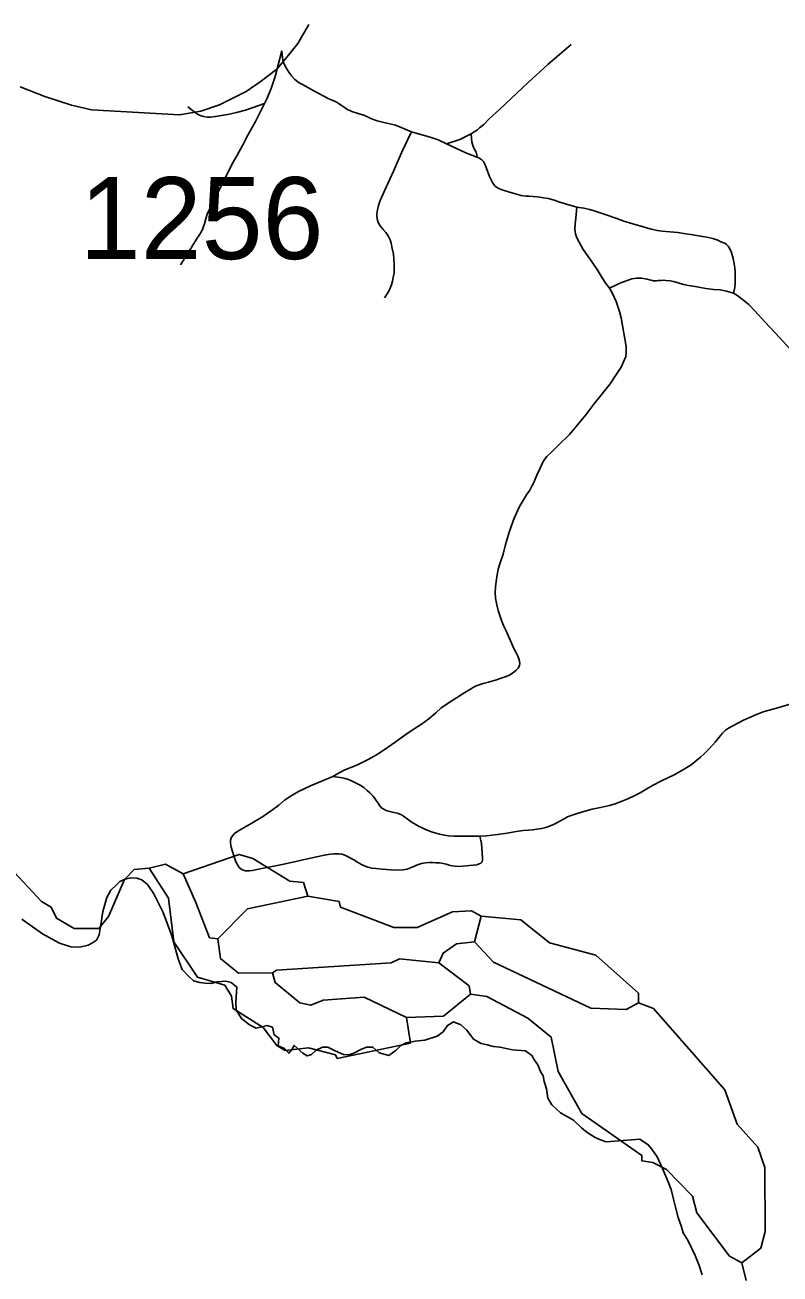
# Model space of a CAD drawing. Extents: x 2093524 to 2270757, y 289120 to 570408.
# Drawn here: x 2117615 to 2122223, y 436115 to 443738 of the extents above; entities that cross this region are included whole.
import ezdxf

# ---------------------------------------------------------------- set-up
doc = ezdxf.new("R2010")
doc.units = 0
for name, color, linetype in [('Exist Boundary Political CountyLine', 7, 'Continuous'), ('Exist Hydrographic Misc Water Feature', 7, 'Continuous'), ('Exist Road Non-System Type 51', 7, 'Continuous'), ('Exist Road Secondary Type 51 Attributed', 7, 'Continuous'), ('Exist Road Secondary Type 51 Number Label', 7, 'Continuous')]:
    doc.layers.add(name, color=color, linetype=linetype)

msp = doc.modelspace()

# ---------------------------------------------------------------- linework, layer by layer
at = {"layer": 'Exist Boundary Political CountyLine'}
for points in [[(2119135.5, 437574), (2119125.8, 437622.2), (2119093.8, 437631.8), (2119026.5, 437615.8), (2118984.8, 437635), (2118936.5, 437673.5), (2118904.5, 437728.1), (2118901.2, 437773), (2118907.8, 437866.1), (2118874, 437893.4), (2118840.2, 437901.4), (2118789, 437898.2), (2118748.8, 437888.6), (2118715.2, 437890.2), (2118683, 437893.4), (2118644.5, 437904.6), (2118614, 437933.5), (2118574, 437973.6), (2118550, 438039.4), (2118511.5, 438179), (2118458.5, 438321.8), (2118402.2, 438434.2), (2118363.8, 438491.9), (2118328.5, 438520.8), (2118298, 438530.5), (2118261, 438532.1), (2118227.5, 438525.6), (2118195.2, 438511.2), (2118171.2, 438488.7), (2118139.2, 438456.6), (2118115, 438413.3), (2118089.5, 438326.7), (2118076.5, 438233.6), (2118068.5, 438185.4), (2118052.5, 438153.3), (2118027, 438135.7), (2118001.2, 438122.8), (2117949.8, 438110), (2117895.2, 438111.6), (2117826.2, 438134.1), (2117722, 438190.2), (2117595.2, 438280.1)], [(2121747.5, 436110.5), (2121729.8, 436166.7), (2121705.8, 436227.7), (2121662.2, 436317.5), (2121632.8, 436365.3), (2121618.8, 436409.2), (2121601.5, 436459.6), (2121586.2, 436523.1), (2121574, 436570.9), (2121557.8, 436630.8), (2121539.5, 436676.8), (2121517.2, 436730.6), (2121495, 436780.5), (2121472.8, 436830.3), (2121440.8, 436876.1), (2121418.5, 436904.2), (2121368.2, 436937.8), (2121265.5, 436929.4), (2121162.8, 436920.9), (2121126.5, 436932.8), (2121094.5, 436948.6), (2121046.2, 436978.4), (2121012.2, 437006.1), (2120962, 437053.9), (2120882.8, 437099), (2120829.8, 437147.2), (2120805.5, 437188.9), (2120797.5, 437245.1), (2120783, 437289), (2120776.8, 437323.7), (2120760.8, 437351), (2120744.8, 437391.1), (2120723.8, 437420), (2120707.8, 437448.9), (2120669.2, 437477.8), (2120590.8, 437482.6), (2120514.2, 437499.5), (2120474.2, 437503.3), (2120436.2, 437513.1), (2120400, 437521), (2120352, 437548.8), (2120335.8, 437570.7), (2120309.5, 437605.8), (2120275.5, 437636.3), (2120229.5, 437654.2), (2120193.8, 437631.9), (2120168, 437593.8), (2120130.2, 437565.8), (2120056.5, 437541.9), (2119995.5, 437535.5), (2119940.8, 437525.9), (2119908.8, 437509.8), (2119880, 437481), (2119835, 437448.9), (2119777.2, 437464.9), (2119738.8, 437500.2), (2119700.2, 437500.2), (2119665, 437484.2), (2119623.2, 437461.7), (2119591, 437452.1), (2119559, 437455.3), (2119507.8, 437477.8), (2119462.8, 437500.2), (2119430.8, 437500.2), (2119392.2, 437481), (2119363.2, 437455.3), (2119337.8, 437445.7), (2119312, 437461.7), (2119257.5, 437509.8), (2119244.5, 437484.2), (2119225.2, 437461.7), (2119199.8, 437490.6), (2119161.2, 437506.7), (2119164.2, 437554.8), (2119135.5, 437574)]]:
    msp.add_lwpolyline(points, dxfattribs=at)
at = {"layer": 'Exist Hydrographic Misc Water Feature'}
for p, q in [((2120357.7, 438141.5), (2120398.7, 438298.1)), ((2119968.7, 437522.7), (2119943.7, 437680.7)), ((2119519.6, 437430), (2119968.7, 437522.7)), ((2122016.8, 436074.4), (2121990.7, 436183.3))]:
    msp.add_line(p, q, dxfattribs=at)
for points in [[(2119340.6, 438421), (2119314.6, 438503.5), (2119231.5, 438511.7), (2119005.6, 438650.7), (2118922.5, 438675.4), (2118581.5, 438557.5)], [(2117774.6, 438353.8), (2117715.6, 438387.8), (2117523.7, 438595)], [(2117774.6, 438353.8), (2117807.6, 438287.5), (2117916.5, 438223), (2118066.6, 438223.3), (2118124.7, 438297.6), (2118223.5, 438522), (2118281.5, 438583.2), (2118373.6, 438591.2)], [(2118581.5, 438557.5), (2118472.6, 438615.4), (2118373.6, 438591.2)], [(2119202.6, 437478.9), (2119152.6, 437509.5), (2119068.7, 437619.3), (2118885.6, 437734.6), (2118876.6, 437810.2), (2118834.6, 437876.7), (2118667.6, 437925.9), (2118524.5, 438142), (2118490.7, 438408.4), (2118373.6, 438591.2)], [(2118791.7, 438159.6), (2118741.7, 438167.2), (2118657.6, 438382.1), (2118581.5, 438557.5)], [(2118791.7, 438159.6), (2118973.6, 438343), (2119340.6, 438421)], [(2120398.7, 438298.1), (2120340.7, 438332.1), (2120223.6, 438324.6), (2120007.7, 438230.5), (2119865.6, 438230), (2119540.5, 438354.6), (2119532.5, 438387.6), (2119340.6, 438421)], [(2121359.8, 437770.5), (2121358.7, 437829.5), (2121099.8, 438061.1), (2120816.6, 438135.7), (2120640.6, 438276.9), (2120398.7, 438298.1)], [(2119125.5, 437952.9), (2118917.6, 437950.5), (2118808.5, 438041.2), (2118791.7, 438159.6)], [(2120141.6, 438014.6), (2120166.6, 438073.1), (2120249.6, 438130.6), (2120357.7, 438141.5)], [(2121359.8, 437770.5), (2121284.7, 437729.3), (2121067.8, 437736.9), (2120474.6, 438017.8), (2120357.7, 438141.5)], [(2119125.5, 437952.9), (2119150.5, 437968.7), (2119850.6, 438013.9), (2119900.6, 438039.1), (2120141.6, 438014.6)], [(2119943.7, 437680.7), (2119684.7, 437803.9), (2119434.5, 437785.9), (2119359.7, 437754.6), (2119292.6, 437769.1), (2119142.5, 437893.5), (2119125.5, 437952.9)], [(2120334.7, 437823.7), (2120325.7, 437873.1), (2120141.6, 438014.6)], [(2119943.7, 437680.7), (2120168.6, 437689.3), (2120334.7, 437823.7)], [(2121379.7, 436805.6), (2121379.7, 436838.4), (2121012.6, 437095.1), (2120869.7, 437350.5), (2120826.6, 437561.3), (2120684.7, 437675.7), (2120434.6, 437808.6), (2120334.7, 437823.7)], [(2121990.7, 436183.3), (2122106.8, 436272.8), (2122131.8, 436374), (2122129.7, 436764.4), (2122087.7, 436889.9), (2121961.8, 437030.2), (2121886.8, 437238.4), (2121450.6, 437735.8), (2121359.8, 437770.5)], [(2119519.6, 437430), (2119510.6, 437453.1), (2119344.7, 437495.8), (2119202.6, 437478.9)], [(2121990.7, 436183.3), (2121915.7, 436224.1), (2121714.7, 436487.2), (2121689.7, 436589.5), (2121529.8, 436753.4), (2121446.7, 436794.5), (2121379.7, 436805.6)]]:
    msp.add_lwpolyline(points, dxfattribs=at)
at = {"layer": 'Exist Road Non-System Type 51'}
for points in [[(2120949.2, 443619), (2120806.6, 443497.5), (2120686, 443386.3), (2120584.9, 443291.3), (2120511.8, 443222.6), (2120448.4, 443165.8), (2120414.8, 443131.5), (2120388.9, 443109.2), (2120375.9, 443098.5), (2120357.2, 443085.1), (2120337.4, 443072.9)], [(2119182.6, 443580.5), (2119155.8, 443478.6), (2119142.7, 443424.1), (2119116.9, 443351), (2119091.6, 443288.1), (2119077.8, 443258.4)], [(2119182.6, 443580.5), (2119187, 443536.6), (2119191.7, 443513.9), (2119203.6, 443486.9), (2119214.6, 443467), (2119224.8, 443450.2), (2119243.5, 443424.9), (2119259.2, 443407.7), (2119272.8, 443397.3), (2119288.5, 443385.8), (2119308.7, 443374), (2119377.1, 443336.6), (2119465.6, 443289.6), (2119483.6, 443281.7), (2119499.7, 443274), (2119515.7, 443266), (2119531.9, 443256.3), (2119547.1, 443246), (2119559.6, 443238), (2119569.2, 443232), (2119586.2, 443220.8), (2119598.3, 443215), (2119610.4, 443209.2), (2119622.3, 443205.3), (2119636.4, 443201.4), (2119659.9, 443194), (2119683.1, 443187.7), (2119704.6, 443178.1), (2119726.7, 443166.4), (2119742.8, 443160.5), (2119764.8, 443152.7), (2119781, 443149), (2119804.8, 443143.3), (2119832.9, 443137.5), (2119875.7, 443125.5), (2119911.2, 443112.4), (2119973.5, 443084.9)], [(2118564.8, 442274.5), (2118611.9, 442347), (2118645.4, 442403.3), (2118666.9, 442437.7), (2118682.7, 442461.8), (2118691.9, 442477.6), (2118700.2, 442496), (2118710, 442524), (2118721.5, 442562.2), (2118727.4, 442582.6), (2118737.2, 442606.3), (2118748.8, 442626.4), (2118768.6, 442664.6), (2118823.4, 442775.1), (2118880.7, 442890), (2118907.5, 442939.8), (2118942.5, 443002.3), (2118976.2, 443064.6), (2119021.2, 443148.9), (2119048.7, 443201.2), (2119077.8, 443258.4)], [(2119077.8, 443258.4), (2119002.3, 443232.7), (2118960.4, 443218.3), (2118906.7, 443203.8), (2118862.7, 443193.3), (2118815, 443184.8), (2118777.2, 443178.4), (2118747.2, 443175.2), (2118727, 443176), (2118704.3, 443179), (2118684.8, 443185.2), (2118672.5, 443190.7), (2118662.4, 443196.7), (2118655.1, 443201.2), (2118646.7, 443209), (2118608.5, 443238.6)], [(2119973.5, 443084.9), (2119918.6, 442972.4), (2119866, 442849.9), (2119809.3, 442725.4), (2119783.9, 442667.2), (2119772.3, 442637), (2119765.8, 442609.1), (2119762.3, 442585), (2119763, 442568.4), (2119766.5, 442545.9), (2119773.4, 442529.2), (2119783.6, 442511.2), (2119801.8, 442489.4), (2119818, 442471.7), (2119832.2, 442451.8), (2119844.5, 442426), (2119850.7, 442406.1), (2119857.1, 442374.1), (2119863.4, 442338.2), (2119865.8, 442310.2), (2119868.1, 442276.3), (2119868.9, 442242.3), (2119867.5, 442222.7), (2119863, 442198.2), (2119857.3, 442174.1), (2119851.5, 442152.1), (2119842.1, 442126.9), (2119833.8, 442110), (2119810.3, 442071.7)], [(2119973.5, 443084.9), (2120023.6, 443071.5), (2120067.8, 443060.1), (2120100, 443049.6), (2120135.9, 443036.7), (2120188.2, 443013.3)], [(2120188.2, 443013.3), (2120244.7, 443030.1), (2120269.5, 443038.2), (2120281.8, 443044.2), (2120301.6, 443054.4), (2120337.4, 443072.9)], [(2120337.4, 443072.9), (2120339.6, 443044.8), (2120342, 443024.4), (2120348.2, 443002.9), (2120357.2, 442982.5), (2120367.8, 442960.9), (2120376.9, 442929.3)], [(2120188.2, 443013.3), (2120244.5, 442985.9), (2120282.5, 442968.4), (2120320.8, 442950.6), (2120348.8, 442941.1), (2120376.9, 442929.3)], [(2120376.9, 442929.3), (2120385.7, 442926.5), (2120403, 442915.6), (2120413.2, 442903.8), (2120421.3, 442887.8), (2120429.5, 442867.9), (2120437.9, 442845.9), (2120450.2, 442814.1), (2120460.4, 442792.3), (2120468.5, 442776.3), (2120477.4, 442764.1), (2120487.6, 442752.9), (2120503.2, 442741.6), (2120521.4, 442733.2), (2120539.1, 442727.1), (2120565.1, 442719.4), (2120599.7, 442709.5), (2120643.3, 442698.2), (2120673.4, 442692.4), (2120691.2, 442692.3), (2120716.3, 442690.6), (2120741.9, 442688.2), (2120757.2, 442686.7), (2120779.4, 442683.7), (2120809.5, 442677.9), (2120843.9, 442669), (2120879.6, 442656.7), (2120919.6, 442645.1), (2120983.8, 442625.8)], [(2120983.8, 442625.8), (2120976.5, 442559.8), (2120972.9, 442521.7), (2120971.3, 442491.7), (2120975.4, 442463.8), (2120983.5, 442439.3), (2120998.1, 442412), (2121022.7, 442368.3), (2121063.1, 442310.7), (2121107.8, 442245.2), (2121138.4, 442195.6), (2121160.7, 442159.7), (2121182.1, 442132.1)], [(2120983.8, 442625.8), (2121025.9, 442620.2), (2121059.9, 442612.5), (2121082, 442604.9), (2121113.4, 442595.2), (2121162.3, 442579.7), (2121220.4, 442558.3), (2121270.7, 442540.9), (2121324.7, 442523.4), (2121387, 442506), (2121437.1, 442492.6), (2121475.1, 442483), (2121503.2, 442479.3), (2121551.2, 442475.7), (2121599.2, 442470.4), (2121623, 442467.1), (2121648.1, 442464.2), (2121679.4, 442459.2), (2121749.3, 442446), (2121775.5, 442442.2), (2121795.4, 442438.5), (2121813.5, 442434.5), (2121843.5, 442424.9), (2121865.7, 442413.1), (2121885.7, 442405.3), (2121893.8, 442399.5), (2121906.8, 442387), (2121918.6, 442367.8), (2121926.4, 442349.8), (2121936.8, 442311.8), (2121943.8, 442280.7), (2121947.7, 442256.2), (2121949.6, 442230), (2121950, 442198), (2121948.8, 442160), (2121946.5, 442136.1), (2121939.1, 442102)], [(2121939.1, 442102), (2121896.9, 442113.7), (2121856.8, 442121.1), (2121818.9, 442122.8), (2121770.8, 442130.2), (2121704.7, 442141.5), (2121664.6, 442147.1), (2121636.1, 442154.9), (2121613.5, 442160.9), (2121594.4, 442166.3), (2121573.9, 442172.1), (2121552.4, 442175.9), (2121526.4, 442178.6), (2121510.4, 442179.6), (2121497.4, 442179.2), (2121480.4, 442178.6), (2121468.4, 442177), (2121459.6, 442176.6), (2121450.4, 442177), (2121436.5, 442180.6), (2121426.3, 442182.6), (2121413.2, 442185.7), (2121400.2, 442188.4), (2121378.3, 442192.2), (2121362.3, 442192.9), (2121346.3, 442191.8), (2121319.4, 442188.2), (2121296.5, 442181.2), (2121262, 442168.3), (2121232.8, 442156.5), (2121182.1, 442132.1)], [(2121182.1, 442132.1), (2121200.7, 442099.8), (2121223.1, 442050.1), (2121243.9, 441989.1), (2121252.9, 441950.9), (2121284.4, 441776.1), (2121283.7, 441738.5), (2121281.4, 441715.4), (2121254.1, 441649.1), (2121220.1, 441600.4), (2121187.3, 441548.3), (2121137.8, 441485.9), (2121086.6, 441423.3), (2121037.3, 441358.9), (2120989.9, 441300.4), (2120938.7, 441237.9), (2120871.4, 441173.2), (2120825.9, 441128.7), (2120800, 441104.5), (2120786.3, 441086.3), (2120776.6, 441070.3), (2120759, 441032.1), (2120741.2, 440994), (2120729.5, 440966.1), (2120721.8, 440949.8), (2120710.3, 440926.9), (2120696.4, 440899.5), (2120676.8, 440869.3), (2120657, 440839.1), (2120640.2, 440808.9), (2120627.5, 440786.9), (2120614, 440758.8), (2120600.2, 440728.5), (2120571.2, 440648.3), (2120548, 440568.1), (2120532.6, 440508.1), (2120515.1, 440455.8), (2120503.6, 440417.6), (2120496, 440381.6), (2120490.4, 440341.5), (2120486.8, 440307.6), (2120485.1, 440273.6), (2120487, 440239.4), (2120494.4, 440198.3), (2120503.5, 440163.9), (2120512.7, 440134.3), (2120521.2, 440108.7), (2120535.9, 440072.4), (2120549.5, 440044.4), (2120563.9, 440012.5), (2120580.3, 439974.8), (2120598.7, 439933), (2120612.9, 439905.1), (2120624.8, 439880.7), (2120631.5, 439863.4), (2120634.7, 439843.7), (2120633.8, 439827.3), (2120625.9, 439813.3), (2120612.6, 439800.1), (2120598.2, 439787), (2120598.2, 439787), (2120584.4, 439776.9), (2120568.4, 439768.6), (2120540, 439758.2), (2120514.4, 439749.7), (2120492.7, 439741.9), (2120465.1, 439732.7), (2120443.8, 439727.3), (2120427.7, 439722.4), (2120411, 439719), (2120393.5, 439712.9), (2120381.2, 439708.8), (2120365.3, 439702.5), (2120346.7, 439691.7), (2120333.5, 439684.3), (2120299.7, 439663.8), (2120226.2, 439617.1), (2120154.7, 439570.5), (2120123.1, 439540.1), (2120079.5, 439503.6), (2120035.9, 439471.3), (2119990.1, 439442.8), (2119938.7, 439408.2), (2119875.1, 439361.5), (2119827.9, 439328.4), (2119777.8, 439294.6), (2119745.8, 439276.3), (2119709.2, 439255.2), (2119684.8, 439243.1), (2119648.6, 439225.2), (2119600.8, 439204.8), (2119567, 439191.5), (2119533.2, 439174.1), (2119493.6, 439151.7)], [(2121939.1, 442102), (2121959.4, 442088.4), (2121975, 442077.5), (2121995, 442061.7), (2122033.2, 442032), (2122069.5, 441994.2), (2122129.9, 441926.6), (2122194.4, 441859.2), (2122311, 441731.8), (2122444, 441600.8), (2122602.9, 441444), (2122739.7, 441314.9), (2122872.3, 441197.9), (2122989, 441100.8), (2123071.6, 441021.3), (2123150, 440951.8), (2123200.3, 440906.2), (2123242.5, 440866.5), (2123277.9, 440836.6)], [(2122291.6, 439594.9), (2122215.7, 439572.4), (2122120, 439545.9), (2122080.3, 439529.5), (2122046.2, 439515.4), (2121999.2, 439494.7), (2121968.7, 439478.9), (2121934.7, 439460.6), (2121908.8, 439446.5), (2121891, 439434.3), (2121871.2, 439415.1), (2121852.4, 439392.2), (2121827.5, 439359.9), (2121811.6, 439341.9), (2121785.8, 439315.8), (2121759.9, 439289.5), (2121738.1, 439269.5), (2121714.5, 439250), (2121680.4, 439223.1), (2121638.7, 439196.9), (2121577, 439162.4), (2121499.2, 439123.9), (2121444.3, 439096.6)], [(2119493.6, 439151.7), (2119358.2, 439094.2), (2119284.6, 439059.5), (2119240.7, 439034.2), (2119199.1, 439006.6), (2119165.5, 438976.3), (2119125.7, 438947.9), (2119094.1, 438925.5), (2119070.2, 438909.4), (2119040.4, 438891), (2119000.7, 438866.6), (2118967.8, 438848.7), (2118938, 438831.3), (2118909.1, 438814), (2118893.3, 438802.7), (2118881.6, 438789.4), (2118873.8, 438777.3), (2118869.9, 438763.2), (2118870.1, 438745.2), (2118874.4, 438719.3), (2118889.8, 438667.2), (2118902.2, 438631), (2118915.5, 438605.9), (2118922.7, 438596.2), (2118933.2, 438587), (2118947.8, 438580.3), (2118961.9, 438576.4), (2118983.5, 438576.2), (2119003.2, 438578.2), (2119029.7, 438583), (2119195.3, 438616.7), (2119394.8, 438660.8), (2119452.6, 438673.4), (2119478.5, 438677.7), (2119500.6, 438679.8), (2119514.6, 438680.2), (2119532.1, 438679.8), (2119550.5, 438676.4), (2119570.5, 438668.6), (2119590.7, 438658.8), (2119610.5, 438649.3), (2119626.5, 438639.9), (2119641.2, 438631.4), (2119669.2, 438613.7), (2119691.2, 438604), (2119707.3, 438598.1), (2119731.4, 438592.4), (2119759.5, 438589.1), (2119797.4, 438585.1), (2119845.4, 438581.6), (2119895.3, 438580.2), (2119923.4, 438582.4), (2119947.8, 438586.5), (2119967.2, 438592.9), (2119993, 438604.4), (2120001.3, 438608.3), (2120016.6, 438615), (2120035.5, 438620.2), (2120058.6, 438623.9), (2120080.8, 438626.1), (2120102.8, 438626.2), (2120121.8, 438624.7), (2120144.6, 438623.4), (2120160.1, 438621.5), (2120184.8, 438615.2), (2120204.9, 438609.4), (2120221.8, 438605.5), (2120240.3, 438603.1), (2120262.9, 438602), (2120372.7, 438613), (2120386.8, 438617.2), (2120396.7, 438621.4), (2120404.7, 438631.4), (2120406.5, 438643.4), (2120408.4, 438655.5), (2120400.7, 438741.3), (2120391, 438787.3)], [(2120391, 438787.3), (2120293, 438786.2), (2120235, 438787.6), (2120199.1, 438789.3), (2120174.9, 438793), (2120144.1, 438799), (2120115.6, 438807), (2120089.2, 438816.1), (2120056.1, 438829.1), (2120034.3, 438839.4), (2120017.3, 438847.9), (2119996.3, 438859.7), (2119981.7, 438868.2), (2119972.2, 438874.8), (2119956, 438886.5), (2119940.1, 438898.5), (2119925.9, 438909.7), (2119912.1, 438918.2), (2119903.7, 438922), (2119889.7, 438927.9), (2119867.7, 438931.7), (2119840.7, 438936.8), (2119825.9, 438941.1), (2119815.6, 438945.1), (2119800.8, 438953), (2119791.3, 438960.8), (2119779.2, 438974.7), (2119769.7, 438988), (2119759, 439004.5), (2119749.9, 439017.8), (2119740.7, 439030.2), (2119720.6, 439052.2), (2119704.2, 439065.9), (2119686.2, 439081.7), (2119665, 439095.9), (2119643.9, 439107.3), (2119623.9, 439117.1), (2119607.8, 439124.9), (2119589.6, 439132.6), (2119569.5, 439138.4), (2119553.6, 439142.3), (2119539.6, 439144.2), (2119493.6, 439151.7)], [(2121444.3, 439096.6), (2121399.7, 439069.3), (2121368.8, 439051.9), (2121333.6, 439032.4), (2121294.1, 439014.6), (2121264.2, 439002.4), (2121216.5, 438984.2), (2121182.5, 438973.9), (2121126.6, 438961.6), (2121076.4, 438951.2), (2121026.7, 438937), (2120984.9, 438924.6), (2120954.1, 438915.4), (2120927.1, 438904.4), (2120905.3, 438892.2), (2120883.2, 438880), (2120860.8, 438867.5), (2120841.4, 438857.9), (2120815.6, 438847.6), (2120793.6, 438839.4), (2120767.7, 438833.3), (2120739.6, 438829.1), (2120715.7, 438825), (2120688.9, 438824.3), (2120656.5, 438822), (2120613.8, 438816.2), (2120558, 438805.9), (2120498, 438797.5), (2120432.8, 438788.8), (2120391, 438787.3)]]:
    msp.add_lwpolyline(points, dxfattribs=at)
at = {"layer": 'Exist Road Secondary Type 51 Attributed'}
msp.add_lwpolyline([(2117585.2, 443361.4), (2117736.2, 443301.5), (2117899.2, 443248.3), (2118021.9, 443220.3), (2118559.2, 443189.1), (2118688.4, 443212.8), (2118802.7, 443249.9), (2118964.4, 443332.9), (2119051.5, 443391), (2119151.4, 443469.1), (2119222.5, 443553), (2119280.6, 443624.1), (2119347.4, 443740.4)], dxfattribs=at)

# ---------------------------------------------------------------- texts
at = {"layer": 'Exist Road Secondary Type 51 Number Label'}
msp.add_text('1256', height=500, dxfattribs=at).set_placement((2117949.6, 442309.3))

doc.saveas('drawing.dxf')
